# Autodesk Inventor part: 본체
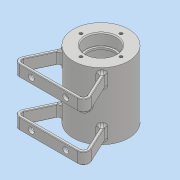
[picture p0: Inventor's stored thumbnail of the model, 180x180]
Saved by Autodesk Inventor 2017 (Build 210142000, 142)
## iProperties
Part Number: 본체
Material: 일반
Document SubType Name: Modeling
Designer: user
Density: 1 g/cm^3
Appearance: 기본값
Author: user
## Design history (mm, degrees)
sketch "스케치1"
  geometry: L1 (21, 0)-(21, -21); L2 (21, -21)-(14, -21); L3 (14, -21)-(14, -23); L4 (14, -23)-(16, -23); L5 (16, -23)-(16, -35); L6 (16, -35)-(29, -35); L7 (29, -35)-(29, 0); L8 (29, 0)-(21, 0); L9 (0, 0)-(0, -35); 1 further point
  constraints: 18 end point, 7 perpendicular, 2 vertical, 1 horizontal alignment, 1 midpoint
  dimensions: "d0" = 35 distance of L9.start L9.end; "d1" = 35 distance of L6.end L7.end; "d2" = 42 diameter of L1 L9; "d3" = 58 diameter of L7 L9; "d4" = 21 distance of L1.start L1.end; "d5" = 32 diameter of L5 L9; "d6" = 28 diameter of L3 L9; "d7" = 12 distance of L4.end L5.end
revolve "회전1" sketch "스케치1" stored, may be unused: angle "d8" = 90 deg
node "작업 평면1"
sketch "스케치2"
  geometry: L1 (-40, -55)-(40, -55); L2 (-40, -55)-(-22.743, -17.993); L3 (40, -55)-(22.743, -17.993); A1 r 29 centre (0, 0) between (-22.743, -17.993) and (22.743, -17.993) reference; 2 further points
  constraints: 6 end point, 2 point on circle, 1 horizontal, 1 midpoint, 1 vertical alignment
  dimensions: "d10" = 80 distance of L1.start L1.end; "d11" = 55 distance of point (0, -55) point (0, 0); "d12" = 65 deg angle of L1 L2; "d13" = 65 deg angle of L1 L3
extrude "돌출1" join sketch "스케치2" distance "d14" = 12; taper "d15" = 0 deg
sketch "스케치3"
  geometry: L1 (-35.291, -52)-(35.291, -52); L2 (35.291, -52)-(20.574, -20.438); L3 (-35.291, -52)-(-20.574, -20.438); L4 (-40, -55)-(40, -55) reference; L5 (-22.743, -17.993)-(-40, -55) reference; L6 (40, -55)-(22.743, -17.993) reference; A1 r 29 centre (0, 0) between (20.574, -20.438) and (-20.574, -20.438) reference; 2 further points
  constraints: 6 end point, 2 parallel, 2 point on circle, 1 horizontal, 2 other
  dimensions: "d16" = 3 distance between parallel lines of L4 L1; "d18" = 3 distance between parallel lines of L3 L5; "d19" = 3 distance between parallel lines of L6 L2
extrude "돌출2" cut sketch "스케치3" distance "d20" = 12; taper "d21" = 0 deg
node "작업 평면2"
sketch "스케치4"
  geometry: L1 (-29, 35)-(29, 35) reference; C1 r 5 at (0, 0); 1 further point
  constraints: 1 centre point, 1 coincident
  dimensions: "d23" = 10 diameter of C1; "d24" = 35 distance from line of C1.centre L1
extrude "돌출3" join sketch "스케치4" stored distance "d25" = 12; taper "d26" = 0 deg
hole "구멍1" diameter "d29" = 5.188; stored, may be unused: countersink angle "d33" = 90 deg, drill point angle "d35" = 118 deg; dims "d27" = 10, "d28" = 10, "d30" = 6, "d31" = 4, "d32" = 2, "d34" = 8
sketch "스케치5"
  geometry: C1 r 1.5 at (0, 0); 1 further point
  constraints: 1 centre point, 1 coincident
  dimensions: "d36" = 3 diameter of C1
extrude "돌출4" cut sketch "스케치5" distance "d37" = 25; taper "d38" = 0 deg
sketch "스케치6"
  geometry: 2 further points
  constraints: 1 vertical alignment
  dimensions: "d39" = 21 distance of point (0, 0) point (0, 21)
hole "구멍2" sketch "스케치6" at (0, 21) diameter "d40" = 3.242; stored, may be unused: countersink angle "d44" = 90 deg, drill point angle "d46" = 118 deg; dims "d41" = 8, "d42" = 4, "d43" = 2, "d45" = 10
sketch "스케치7"
  geometry: L1 (0, 12)-(80, 12) reference; C1 r 3 at (58, 6); C2 r 3 at (22, 6); 1 further point
  constraints: 2 centre point, 1 horizontal alignment
  dimensions: "d50" = 6 diameter of C1; "d51" = 6 diameter of C2; "d52" = 36 distance of C2.centre C1.centre; "d53" = 18 horizontal distance of C1.centre point (40, -18); "d54" = 6 distance from line of L1 C1.centre
extrude "돌출5" cut sketch "스케치7" distance "d55" = 5; taper "d56" = 0 deg
sketch "스케치8"
  geometry: L1 (0, 0)-(10.945, -30.07); L2 (0, 0)-(0, -29)
  constraints: 4 end point, 1 vertical, 1 vertical alignment, 1 other
  dimensions: "d57" = 20 deg angle of L1 L2; "d58" = 32 distance of L1.start L1.end
node "작업 평면3"
sketch "스케치9"
  geometry: C1 r 6 at (0, 0); 1 further point
  constraints: 1 centre point, 1 coincident
  dimensions: "d59" = 12 diameter of C1
extrude "돌출6" join sketch "스케치9" stored distance "d60" = 5; taper "d61" = 0 deg
sketch "스케치10"
  geometry: 2 further points
  constraints: 1 coincident
hole "구멍3" sketch "스케치10" at (0, 0) diameter "d62" = 5.188; stored, may be unused: countersink angle "d66" = 90 deg, drill point angle "d68" = 0 deg; dims "d63" = 12, "d64" = 4, "d65" = 2, "d67" = 20
fillet "모깎기1" dims "d69" = 6
fillet "모깎기2" dims "d70" = 3
fillet "모깎기3" dims "d71" = 0.5
fillet "모깎기4" dims "d72" = 1
fillet "모깎기5" dims "d73" = 3
node "작업 평면4"
sketch "스케치11"
  geometry: L1 (-29, -35)-(29, -35) reference; L2 (-29, 35)-(-29, -35) reference; 2 further points
  constraints: 1 other
  dimensions: "d75" = 35 distance from line of point (0, 0) L1; "d76" = 29 distance from line of point (0, 0) L2
feature "엠보싱1" sketch "스케치11" dims "d0" = 35, "d1" = 35, "d2" = 42, "d3" = 58, "d4" = 21, "d5" = 32, "d6" = 28, "d7" = 12, "d10" = 80, "d11" = 55, "d12" = 65 deg, "d13" = 65 deg, "d77" = 0.5, "d78" = 0
fillet "모깎기6" dims "d79" = 0.3
fillet "모깎기7" dims "d80" = 3
chamfer "모따기1" distance "d81" = 1; stored, may be unused: second distance "d82" = 2, angle "d83" = 45 deg
node "솔리드1"
mirror "미러1"
mirror "미러2"
pattern_circular "원형 패턴1" dims angle "d48" = 360 deg
mirror "미러3"
mirror "미러4"
other parameters: "d9" = 18, "d22" = 32, "d74" = -29
